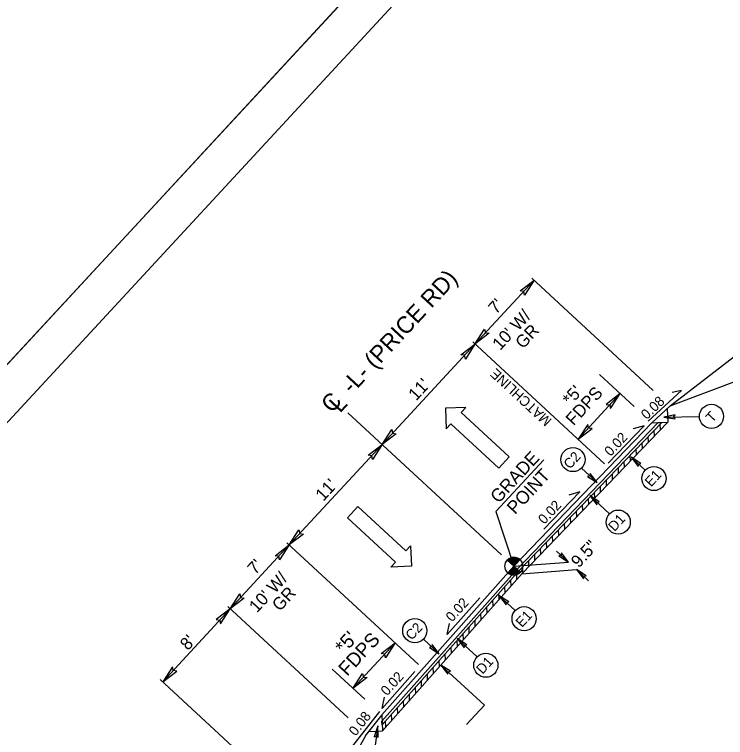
# Model space of a CAD drawing. Extents: x 1768274 to 1769121, y 999922 to 1000687.
# Drawn here: x 1768971.2 to 1769052.4, y 999972.2 to 1000054.9 of the extents above; entities that cross this region are included whole.
import ezdxf

# ---------------------------------------------------------------- set-up
doc = ezdxf.new("R2010")
doc.units = 0
for name, color, linetype in [('E_NCDOT_Terrain_Model_Contour_Imported', 7, 'Continuous'), ('E_NCDOT_Terrain_Model_Contour_Major', 7, 'Continuous'), ('E_NCDOT_Terrain_Model_Contour_Minor', 7, 'Continuous'), ('E_NCDOT_Terrain_Model_Spot_Elevation', 7, 'Continuous'), ('E_NCDOT_Terrain_Model_Triangles', 7, 'Continuous')]:
    doc.layers.add(name, color=color, linetype=linetype)

msp = doc.modelspace()

# ---------------------------------------------------------------- linework, layer by layer
at = {"layer": 'E_NCDOT_Terrain_Model_Contour_Imported'}
msp.add_lwpolyline([(1768737.288, 1000073.608), (1768947.711, 1000301.251), (1769102.655, 1000158.029), (1768892.232, 999930.385)], close=True, dxfattribs=at)
at = {"layer": 'E_NCDOT_Terrain_Model_Contour_Major'}
msp.add_line((1768892.229, 999930.381), (1769116.231, 1000172.715), dxfattribs=at)
at = {"layer": 'E_NCDOT_Terrain_Model_Contour_Minor'}
msp.add_lwpolyline([(1769045.162, 1000008.25), (1769028.837, 999991.283), (1769013.196, 999973.668), (1769013.179, 999974.095), (1769028.616, 999991.48), (1769044.736, 1000008.234)], close=True, dxfattribs=at)
at = {"layer": 'E_NCDOT_Terrain_Model_Spot_Elevation'}
msp.add_lwpolyline([(1768729.032, 1000071.305), (1768959.819, 1000320.98), (1769121.372, 1000171.648), (1768890.585, 999921.973)], close=True, dxfattribs=at)
at = {"layer": 'E_NCDOT_Terrain_Model_Triangles'}
for p, q in [((1769023.811, 1000017.206), (1769030.563, 1000024.51)), ((1769044.187, 1000011.917), (1769030.304, 1000024.75)), ((1769046.112, 1000010.138), (1769063.78, 1000023.837)), ((1769046.112, 1000010.138), (1769069.178, 1000018.847)), ((1769013.202, 1000005.728), (1769023.811, 1000017.206)), ((1769038.616, 1000003.521), (1769023.552, 1000017.446)), ((1769041.999, 1000010.07), (1769038.028, 1000013.74)), ((1769047.398, 1000011.914), (1769043.617, 1000008.394)), ((1769047.398, 1000011.914), (1769046.352, 1000011.679)), ((1769035.586, 1000006.322), (1769040.409, 1000011.54)), ((1769022.777, 1000009.967), (1769020.423, 1000009.894)), ((1769020.423, 1000009.894), (1769020.498, 1000007.502)), ((1769022.234, 1000009.38), (1769022.777, 1000009.967)), ((1769027.712, 1000004.316), (1769022.234, 1000009.38)), ((1769044.016, 1000008.205), (1769046.112, 1000010.138)), ((1769045.784, 1000009.835), (1769045.845, 1000008.277)), ((1769026.825, 999993.135), (1769009.289, 1000009.345)), ((1769045.39, 1000008.865), (1769049.453, 1000008.919)), ((1769020.498, 1000007.502), (1769021.04, 1000008.089)), ((1769021.04, 1000008.089), (1769026.519, 1000003.025)), ((1769028.25, 999991.818), (1769044.016, 1000008.205)), ((1769028.616, 999991.48), (1769044.736, 1000008.234)), ((1769028.837, 999991.283), (1769045.162, 1000008.25)), ((1769029.192, 999990.968), (1769045.845, 1000008.277)), ((1769043.144, 1000007.863), (1769039.04, 1000003.598)), ((1769043.144, 1000007.863), (1769041.895, 1000007.502)), ((1769044.016, 1000008.205), (1769045.845, 1000008.277)), ((1769045.001, 1000007.4), (1769044.975, 1000008.056)), ((1769044.318, 1000006.69), (1769044.292, 1000007.346)), ((1769043.635, 1000005.98), (1769043.609, 1000006.636)), ((1769002.592, 999994.25), (1769013.202, 1000005.728)), ((1769042.952, 1000005.27), (1769042.926, 1000005.926)), ((1769041.585, 1000003.85), (1769041.56, 1000004.506)), ((1769042.268, 1000004.56), (1769042.243, 1000005.216)), ((1769026.199, 999998.068), (1769031.659, 1000003.975)), ((1769026.519, 1000003.025), (1769027.712, 1000004.316)), ((1769040.902, 1000003.14), (1769040.876, 1000003.796)), ((1769041.668, 1000004.264), (1769043.259, 1000002.792)), ((1769037.778, 1000001.368), (1769035.982, 1000003.029)), ((1769040.219, 1000002.43), (1769040.193, 1000003.086)), ((1769039.536, 1000001.72), (1769039.51, 1000002.376)), ((1769038.853, 1000001.01), (1769038.827, 1000001.666)), ((1769035.779, 1000000.31), (1769031.675, 999996.044)), ((1769035.779, 1000000.31), (1769034.53, 999999.949)), ((1769038.17, 1000000.3), (1769038.144, 1000000.956)), ((1769036.803, 999998.88), (1769036.778, 999999.536)), ((1769036.919, 999999.898), (1769039.18, 999997.808)), ((1769037.487, 999999.59), (1769037.461, 1000000.246)), ((1769009.244, 999997.345), (1769010.438, 999998.636)), ((1769010.438, 999998.636), (1769015.916, 999993.572)), ((1769036.12, 999998.17), (1769036.095, 999998.826)), ((1769026.199, 999998.068), (1769028.25, 999991.818)), ((1769035.437, 999997.46), (1769035.411, 999998.116)), ((1769014.722, 999992.281), (1769009.244, 999997.345)), ((1769034.754, 999996.75), (1769034.728, 999997.406)), ((1769034.071, 999996.04), (1769034.045, 999996.696)), ((1769033.388, 999995.33), (1769033.362, 999995.986)), ((1769017.367, 999980.592), (1769002.316, 999994.505)), ((1769032.022, 999993.91), (1769031.996, 999994.566)), ((1769032.705, 999994.62), (1769032.679, 999995.276)), ((1768995.84, 999986.946), (1769002.592, 999994.25)), ((1769015.916, 999993.572), (1769016.458, 999994.159)), ((1769016.458, 999994.159), (1769016.57, 999991.807)), ((1769031.338, 999993.2), (1769031.313, 999993.856)), ((1769030.655, 999992.49), (1769030.63, 999993.146)), ((1769034.493, 999992.292), (1769033.131, 999993.552)), ((1769014.18, 999991.694), (1769014.722, 999992.281)), ((1769028.25, 999991.818), (1769027.502, 999992.509)), ((1769028.94, 999992.566), (1769028.25, 999991.818)), ((1769028.25, 999991.818), (1769034.493, 999992.292)), ((1769029.972, 999991.78), (1769029.946, 999992.436)), ((1769028.25, 999991.818), (1769013.151, 999974.814)), ((1769028.616, 999991.48), (1769013.179, 999974.095)), ((1769028.837, 999991.283), (1769013.196, 999973.668)), ((1769016.57, 999991.807), (1769014.18, 999991.694)), ((1769027.559, 999991.071), (1769028.25, 999991.818)), ((1769028.995, 999991.126), (1769028.25, 999991.818)), ((1769028.25, 999991.818), (1769028.995, 999991.126)), ((1769029.181, 999990.957), (1769035.425, 999991.431)), ((1769029.289, 999991.07), (1769029.263, 999991.726)), ((1769036.798, 999990.162), (1769035.425, 999991.431)), ((1769029.192, 999990.968), (1769013.223, 999972.984)), ((1769028.608, 999990.311), (1769028.581, 999990.994)), ((1769027.927, 999989.544), (1769027.9, 999990.227)), ((1769027.246, 999988.777), (1769027.219, 999989.461)), ((1769020.631, 999984.004), (1769024.372, 999988.218)), ((1769025.884, 999987.244), (1769025.857, 999987.927)), ((1769026.565, 999988.011), (1769026.538, 999988.694)), ((1769026.592, 999988.441), (1769028.413, 999986.758)), ((1769009.316, 999974.489), (1768995.564, 999987.201)), ((1769025.203, 999986.477), (1769025.177, 999987.16)), ((1768995.84, 999986.946), (1768988.123, 999978.598)), ((1769024.523, 999985.71), (1769024.496, 999986.393)), ((1769023.842, 999984.943), (1769023.815, 999985.626)), ((1769020.631, 999984.004), (1769020.892, 999985.278)), ((1769023.161, 999984.177), (1769023.134, 999984.86)), ((1769022.48, 999983.41), (1769022.453, 999984.093)), ((1769014.693, 999983.064), (1769009.87, 999977.847)), ((1769019.706, 999981.817), (1769017.91, 999983.477)), ((1769021.799, 999982.643), (1769021.772, 999983.326)), ((1769021.788, 999983.54), (1769024.048, 999981.451)), ((1769021.118, 999981.876), (1769021.091, 999982.559)), ((1769020.437, 999981.109), (1769020.41, 999981.792)), ((1769019.756, 999980.342), (1769019.729, 999981.026)), ((1769019.92, 999980.519), (1769024.886, 999975.929)), ((1769011.217, 999976.602), (1769007.489, 999980.047)), ((1769013.194, 999975.56), (1769016.936, 999979.774)), ((1769019.075, 999979.576), (1769019.049, 999980.259)), ((1769004.6, 999963.367), (1768987.848, 999978.853)), ((1769018.395, 999978.809), (1769018.368, 999979.492)), ((1769017.714, 999978.042), (1769017.687, 999978.725)), ((1769016.338, 999976.493), (1769016.312, 999977.176)), ((1769017.033, 999977.276), (1769017.007, 999977.959)), ((1769013.194, 999975.56), (1769013.456, 999976.833)), ((1769015.672, 999975.742), (1769015.645, 999976.425)), ((1769014.991, 999974.976), (1769014.964, 999975.659)), ((1769024.886, 999975.929), (1769022.843, 999973.719)), ((1769009.719, 999971.152), (1769012.931, 999975.197)), ((1769013.151, 999974.814), (1769011.389, 999972.573)), ((1769013.151, 999974.814), (1769013.223, 999972.984)), ((1769014.31, 999974.209), (1769014.283, 999974.892)), ((1769013.63, 999973.442), (1769013.603, 999974.126)), ((1769012.705, 999973.568), (1769012.06, 999968.688)), ((1769011.389, 999972.573), (1769005.759, 999962.296)), ((1769011.664, 999972.923), (1769013.223, 999972.984))]:
    msp.add_line(p, q, dxfattribs=at)
for points in [[(1769028.954, 1000023.277), (1769030.563, 1000024.51), (1769029.46, 1000022.794), (1769029.373, 1000023.223)], [(1769025.42, 1000018.44), (1769023.811, 1000017.206), (1769024.914, 1000018.923), (1769025.002, 1000018.494)], [(1769022.203, 1000015.973), (1769023.811, 1000017.206), (1769022.709, 1000015.49), (1769022.621, 1000015.918)], [(1769039.306, 1000009.839), (1769040.409, 1000011.54), (1769038.784, 1000010.305), (1769039.219, 1000010.252)], [(1769046.68, 1000009.105), (1769045.39, 1000008.865), (1769046.693, 1000008.652), (1769046.525, 1000008.88)], [(1769036.69, 1000008.023), (1769035.586, 1000006.322), (1769037.211, 1000007.556), (1769036.777, 1000007.61)], [(1769014.81, 1000006.962), (1769013.202, 1000005.728), (1769014.304, 1000007.444), (1769014.392, 1000007.016)], [(1769011.593, 1000004.494), (1769013.202, 1000005.728), (1769012.099, 1000004.012), (1769012.011, 1000004.44)], [(1769042.768, 1000003.55), (1769041.668, 1000004.264), (1769042.466, 1000003.212), (1769042.501, 1000003.493)], [(1769036.678, 1000002.082), (1769037.778, 1000001.368), (1769036.98, 1000002.419), (1769036.945, 1000002.139)], [(1769038.019, 999999.184), (1769036.919, 999999.898), (1769037.717, 999998.847), (1769037.752, 999999.128)], [(1769004.2, 999995.484), (1769002.592, 999994.25), (1769003.694, 999995.966), (1769003.782, 999995.538)], [(1769000.983, 999993.016), (1769002.592, 999994.25), (1769001.489, 999992.534), (1769001.401, 999992.962)], [(1769033.392, 999993.006), (1769034.493, 999992.292), (1769033.694, 999993.343), (1769033.659, 999993.062)], [(1769036.525, 999990.717), (1769035.425, 999991.431), (1769036.223, 999990.38), (1769036.258, 999990.661)], [(1768997.449, 999988.179), (1768995.84, 999986.945), (1768996.943, 999988.662), (1768997.03, 999988.233)], [(1769027.692, 999987.727), (1769026.592, 999988.441), (1769027.39, 999987.39), (1769027.425, 999987.671)], [(1768994.736, 999985.245), (1768995.84, 999986.946), (1768994.215, 999985.711), (1768994.649, 999985.658)], [(1769013.084, 999981.831), (1769014.693, 999983.064), (1769013.59, 999981.348), (1769013.502, 999981.776)], [(1769022.888, 999982.826), (1769021.788, 999983.54), (1769022.586, 999982.489), (1769022.621, 999982.77)], [(1769018.606, 999982.531), (1769019.706, 999981.817), (1769018.908, 999982.868), (1769018.873, 999982.587)], [(1769021.02, 999979.805), (1769019.92, 999980.519), (1769020.718, 999979.468), (1769020.753, 999979.749)], [(1768989.227, 999980.299), (1768988.124, 999978.598), (1768989.748, 999979.832), (1768989.314, 999979.886)], [(1769011.479, 999979.08), (1769009.87, 999977.847), (1769010.973, 999979.563), (1769011.06, 999979.135)], [(1769012.756, 999972.257), (1769012.705, 999973.568), (1769012.307, 999972.309), (1769012.556, 999972.443)]]:
    msp.add_lwpolyline(points, close=True, dxfattribs=at)
for points in [[(1769027.508, 999992.516), (1769027.508, 999992.516), (1769028.256, 999991.825)], [(1769027.522, 999992.531), (1769028.27, 999991.84)], [(1769027.538, 999992.544), (1769028.283, 999991.855)], [(1769027.552, 999992.559), (1769028.297, 999991.87)], [(1769027.567, 999992.572), (1769028.311, 999991.885)], [(1769027.582, 999992.586), (1769028.325, 999991.9)], [(1769027.598, 999992.599), (1769028.339, 999991.915)], [(1769027.613, 999992.613), (1769028.352, 999991.93)], [(1769027.629, 999992.626), (1769028.366, 999991.945)], [(1769027.646, 999992.638), (1769028.38, 999991.959)], [(1769027.663, 999992.65), (1769028.394, 999991.974)], [(1769027.68, 999992.662), (1769028.408, 999991.989)], [(1769027.697, 999992.674), (1769028.422, 999992.004)], [(1769027.716, 999992.684), (1769028.435, 999992.019)], [(1769027.733, 999992.696), (1769028.449, 999992.034)], [(1769027.752, 999992.706), (1769028.463, 999992.049)], [(1769027.771, 999992.716), (1769028.477, 999992.064)], [(1769027.79, 999992.727), (1769028.491, 999992.079)], [(1769027.81, 999992.736), (1769028.504, 999992.094)], [(1769027.831, 999992.744), (1769028.518, 999992.109)], [(1769027.851, 999992.753), (1769028.532, 999992.124)], [(1769027.872, 999992.762), (1769028.546, 999992.139)], [(1769027.892, 999992.771), (1769028.56, 999992.154)], [(1769027.914, 999992.778), (1769028.573, 999992.169)], [(1769027.936, 999992.785), (1769028.587, 999992.184)], [(1769027.958, 999992.793), (1769028.601, 999992.199)], [(1769027.98, 999992.8), (1769028.615, 999992.214)], [(1769028.004, 999992.806), (1769028.629, 999992.228)], [(1769028.028, 999992.811), (1769028.643, 999992.243)], [(1769028.054, 999992.816), (1769028.656, 999992.258)], [(1769028.077, 999992.821), (1769028.67, 999992.273)], [(1769028.103, 999992.826), (1769028.684, 999992.288)], [(1769028.13, 999992.828), (1769028.698, 999992.303)], [(1769028.157, 999992.831), (1769028.712, 999992.318)], [(1769028.184, 999992.833), (1769028.725, 999992.333)], [(1769028.213, 999992.835), (1769028.739, 999992.348)], [(1769028.242, 999992.836), (1769028.753, 999992.363)], [(1769028.272, 999992.835), (1769028.767, 999992.378)], [(1769028.304, 999992.833), (1769028.781, 999992.393)], [(1769028.336, 999992.832), (1769028.795, 999992.408)], [(1769028.37, 999992.828), (1769028.808, 999992.423)], [(1769028.405, 999992.823), (1769028.822, 999992.438)], [(1769028.442, 999992.816), (1769028.836, 999992.453)], [(1769028.481, 999992.808), (1769028.85, 999992.468)], [(1769028.521, 999992.799), (1769028.864, 999992.483)], [(1769028.567, 999992.785), (1769028.877, 999992.497)], [(1769028.616, 999992.767), (1769028.891, 999992.512)], [(1769028.671, 999992.744), (1769028.905, 999992.527)], [(1769028.736, 999992.711), (1769028.919, 999992.542)], [(1769028.826, 999992.656), (1769028.933, 999992.557)], [(1769027.672, 999991.194), (1769028.084, 999990.813)], [(1769027.686, 999991.209), (1769028.12, 999990.808)], [(1769027.7, 999991.224), (1769028.153, 999990.805)], [(1769027.714, 999991.239), (1769028.185, 999990.803)], [(1769027.728, 999991.254), (1769028.218, 999990.801)], [(1769027.742, 999991.269), (1769028.248, 999990.8)], [(1769027.755, 999991.284), (1769028.278, 999990.8)], [(1769027.769, 999991.299), (1769028.307, 999990.801)], [(1769027.783, 999991.313), (1769028.334, 999990.804)], [(1769027.797, 999991.328), (1769028.361, 999990.807)], [(1769027.811, 999991.343), (1769028.388, 999990.809)], [(1769027.824, 999991.358), (1769028.414, 999990.813)], [(1769027.838, 999991.373), (1769028.439, 999990.818)], [(1769027.852, 999991.388), (1769028.463, 999990.823)], [(1769027.866, 999991.403), (1769028.487, 999990.829)], [(1769027.88, 999991.418), (1769028.511, 999990.835)], [(1769027.893, 999991.433), (1769028.534, 999990.841)], [(1769027.907, 999991.448), (1769028.557, 999990.848)], [(1769027.921, 999991.463), (1769028.579, 999990.855)], [(1769027.935, 999991.478), (1769028.601, 999990.862)], [(1769027.949, 999991.493), (1769028.621, 999990.871)], [(1769027.963, 999991.508), (1769028.642, 999990.88)], [(1769027.976, 999991.523), (1769028.662, 999990.889)], [(1769027.99, 999991.538), (1769028.683, 999990.898)], [(1769028.004, 999991.553), (1769028.703, 999990.906)], [(1769028.018, 999991.568), (1769028.722, 999990.917)], [(1769028.032, 999991.582), (1769028.741, 999990.927)], [(1769028.045, 999991.597), (1769028.759, 999990.937)], [(1769028.059, 999991.612), (1769028.777, 999990.949)], [(1769028.073, 999991.627), (1769028.795, 999990.96)], [(1769028.087, 999991.642), (1769028.813, 999990.972)], [(1769028.101, 999991.657), (1769028.83, 999990.983)], [(1769028.115, 999991.672), (1769028.847, 999990.995)], [(1769028.128, 999991.687), (1769028.864, 999991.007)], [(1769028.142, 999991.702), (1769028.879, 999991.021)], [(1769028.156, 999991.717), (1769028.897, 999991.032)], [(1769028.17, 999991.732), (1769028.912, 999991.046)], [(1769028.184, 999991.747), (1769028.927, 999991.059)], [(1769028.197, 999991.762), (1769028.943, 999991.073)], [(1769028.211, 999991.777), (1769028.957, 999991.088)], [(1769028.225, 999991.792), (1769028.972, 999991.101)], [(1769028.239, 999991.807), (1769028.986, 999991.116), (1769028.986, 999991.116)], [(1769027.562, 999991.074), (1769027.643, 999990.999)], [(1769027.576, 999991.089), (1769027.745, 999990.933)], [(1769027.59, 999991.104), (1769027.812, 999990.899)], [(1769027.603, 999991.119), (1769027.871, 999990.872)], [(1769027.617, 999991.134), (1769027.919, 999990.855)], [(1769027.631, 999991.149), (1769027.965, 999990.841)], [(1769027.645, 999991.164), (1769028.007, 999990.829)], [(1769027.659, 999991.179), (1769028.047, 999990.82)]]:
    msp.add_lwpolyline(points, dxfattribs=at)
for centre, radius in [((1769050.834, 1000008.937), 1.381), ((1769035.003, 1000004.003), 1.381), ((1769044.26, 1000001.84), 1.381), ((1769040.18, 999996.856), 1.381), ((1769028.249, 999991.818), 1.018), ((1769029.426, 999985.818), 1.381), ((1769016.931, 999984.451), 1.381), ((1769025.049, 999980.498), 1.381)]:
    msp.add_circle(centre, radius, dxfattribs=at)
for start, end in [(47.2417, 137.2417), (227.2417, 317.2417)]:
    msp.add_arc((1769028.249, 999991.818), 1.018, start, end, dxfattribs=at)

# ---------------------------------------------------------------- texts
for s, height, rotation, p in [('-L- (PRICE RD)', 1.93252, 47.25123, (1769009.767, 1000011.408)), ("7'", 1.421, 47.25099, (1769026.232, 1000020.538)), ("10' W/", 1.421, 47.25099, (1769026.692, 1000016.415)), ('GR', 1.421, 47.25099, (1769029.313, 1000016.572)), ('MATCHLINE', 1.1368, 137.25123, (1769032.664, 1000008.54)), ("11'", 1.421, 47.25099, (1769017.091, 1000010.648)), ("*5' ", 1.421, 47.25099, (1769034.708, 1000010.083)), ('FDPS', 1.421, 47.25099, (1769035.075, 1000007.801)), ('C', 1.933, 47.25123, (1769007.458, 1000009.223)), ('0.08', 1.1368, 43.02586, (1769043.42, 1000008.512)), ('L', 1.934, 47.19813, (1769008.379, 1000009.247)), ('T', 1.137, 47.25094, (1769050.905, 1000008.159)), ('0.02', 1.1368, 46.71099, (1769039.3, 1000004.303)), ('GRADE', 1.4834, 47.25123, (1769026.501, 999998.916)), ('C2', 1.1368, 47.25123, (1769034.654, 1000002.838)), ('POINT', 1.4834, 47.25123, (1769028.394, 999997.653)), ('E1', 1.1368, 47.25123, (1769043.939, 1000000.81)), ("11'", 1.421, 47.25099, (1769006.481, 999999.17)), ('0.02', 1.1368, 46.71099, (1769031.731, 999996.538)), ('D1', 1.1368, 47.25123, (1769039.756, 999995.713)), ('9.5"', 1.421, 47.25099, (1769035.679, 999991.548)), ("7'", 1.421, 47.25099, (1768998.707, 999990.76)), ("10' W/", 1.421, 47.25099, (1768998.894, 999986.419)), ('GR', 1.421, 47.25099, (1769001.515, 999986.576)), ('0.02', 1.1368, 47.79146, (1769021.196, 999985.378)), ('E1', 1.1368, 47.25123, (1769029.18, 999984.746)), ('C2', 1.1368, 47.25123, (1769016.583, 999983.289)), ("8'", 1.421, 47.25099, (1768991.004, 999982.111)), ("*5' ", 1.5915, 47.25099, (1769008.832, 999981.686)), ('FDPS', 1.5915, 47.25099, (1769009.208, 999979.163)), ('D1', 1.1368, 47.25123, (1769024.668, 999979.403)), ('0.02', 1.1368, 47.79146, (1769013.76, 999976.934)), ('0.08', 1.1368, 51.82483, (1769010.175, 999972.327))]:
    msp.add_text(s, height=height, rotation=rotation, dxfattribs=at).set_placement(p)

doc.saveas('drawing.dxf')
